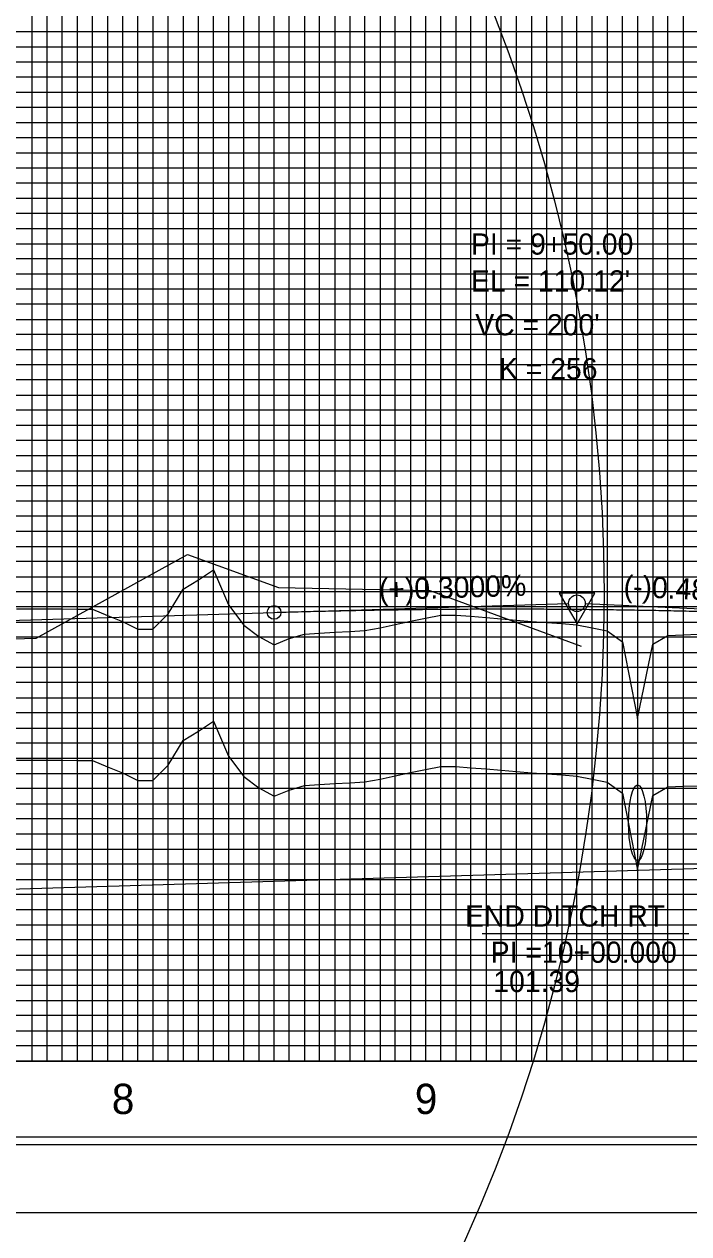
# Model space of a CAD drawing. Extents: x 2345490 to 2436403, y 465165 to 573888.
# Drawn here: x 2411662.8 to 2411882.2, y 527715 to 528114.5 of the extents above; entities that cross this region are included whole.
import ezdxf

# ---------------------------------------------------------------- set-up
doc = ezdxf.new("R2010")
doc.units = 0
for name, color, linetype in [('Old_Level_1', 7, 'Continuous'), ('Old_Level_18', 7, 'Continuous'), ('Old_Level_2', 7, 'Continuous'), ('Old_Level_3', 7, 'Continuous'), ('Old_Level_4', 7, 'Continuous'), ('Old_Level_41', 7, 'Continuous'), ('Old_Level_42', 7, 'Continuous'), ('Old_Level_43', 7, 'Continuous'), ('Old_Level_50', 7, 'Continuous'), ('Old_Level_51', 7, 'Continuous'), ('Old_Level_62', 7, 'Continuous'), ('Old_Level_63', 7, 'Continuous')]:
    doc.layers.add(name, color=color, linetype=linetype)

msp = doc.modelspace()

# ---------------------------------------------------------------- linework, layer by layer
at = {"layer": 'Old_Level_1'}
msp.add_lwpolyline([(2411660.325, 527871.39675), (2411665.325, 527871.40325), (2411670.325, 527871.4), (2411675.325, 527871.387), (2411680.325, 527871.364), (2411685.325, 527871.33125), (2411690.325, 527869.2045), (2411695.325, 527867.2145), (2411700.325, 527864.6685), (2411705.325, 527864.74925), (2411710.325, 527869.74075), (2411715.325, 527877.96775), (2411720.325, 527881.0285), (2411725.325, 527884.32975), (2411730.325, 527872.71875), (2411735.325, 527866.0195), (2411740.325, 527862.33025), (2411745.325, 527859.488), (2411750.325, 527861.572), (2411755.325, 527863.093), (2411760.325, 527863.4175), (2411765.325, 527863.7135), (2411770.325, 527863.98125), (2411775.325, 527864.2205), (2411780.325, 527865.149), (2411785.325, 527866.243), (2411790.325, 527867.30725), (2411795.325, 527868.34125), (2411800.325, 527869.3455), (2411805.325, 527869.375), (2411810.325, 527868.94925), (2411815.325, 527868.52725), (2411820.325, 527868.1085), (2411825.325, 527867.6935), (2411830.325, 527867.28175), (2411835.325, 527866.8735), (2411840.325, 527866.55275), (2411845.325, 527866.1855), (2411850.325, 527865.1565), (2411855.325, 527864.12875), (2411860.325, 527860.572), (2411865.325, 527835.20325), (2411870.325, 527859.79525), (2411875.325, 527862.6535), (2411880.325, 527862.82425), (2411885.325, 527862.99775)], dxfattribs=at)
at = {"layer": 'Old_Level_18'}
msp.add_lwpolyline([(2412345.325, 528797.04275), (2410845.325, 528797.04275), (2410845.325, 527747.04275), (2412345.325, 527747.04275)], close=True, dxfattribs=at)
at = {"layer": 'Old_Level_2'}
for p, q in [((2411745.325, 527920.243), (2411842.57625, 527923.16075)), ((2411945.325, 527918.443), (2411848.072, 527923.11125)), ((2411490.325, 527912.593), (2411745.325, 527920.243))]:
    msp.add_line(p, q, dxfattribs=at)
msp.add_lwpolyline([(2411851.19225, 527926.6255), (2411839.44975, 527926.611), (2411845.33325, 527916.49275)], close=True, dxfattribs=at)
for centre, radius in [((2411845.325, 527923.243), 2.75), ((2411745.325, 527920.243), 2.25)]:
    msp.add_circle(centre, radius, dxfattribs=at)
msp.add_spline([(2411745.325, 527920.243), (2411749.325, 527920.36), (2411753.325, 527920.47075), (2411757.325, 527920.575), (2411761.325, 527920.67325), (2411765.325, 527920.765), (2411769.325, 527920.85075), (2411773.325, 527920.93025), (2411777.325, 527921.0035), (2411781.325, 527921.0705), (2411785.325, 527921.131), (2411789.325, 527921.1855), (2411793.325, 527921.23375), (2411797.325, 527921.27575), (2411801.325, 527921.3115), (2411805.325, 527921.341), (2411809.325, 527921.3645), (2411813.325, 527921.3815), (2411817.325, 527921.39225), (2411821.325, 527921.39675), (2411825.325, 527921.395), (2411829.325, 527921.38725), (2411833.325, 527921.373), (2411837.325, 527921.35275), (2411841.325, 527921.326), (2411845.325, 527921.293), (2411849.325, 527921.254), (2411853.325, 527921.20875), (2411857.325, 527921.157), (2411861.325, 527921.09925), (2411865.325, 527921.035), (2411869.325, 527920.96475), (2411873.325, 527920.88825), (2411877.325, 527920.8055), (2411881.325, 527920.7165), (2411885.325, 527920.621), (2411889.325, 527920.5195), (2411893.325, 527920.41175), (2411897.325, 527920.29775), (2411901.325, 527920.1775), (2411905.325, 527920.051), (2411909.325, 527919.9185), (2411913.325, 527919.7795), (2411917.325, 527919.63425), (2411921.325, 527919.48275), (2411925.325, 527919.325), (2411929.325, 527919.16125), (2411933.325, 527918.991), (2411937.325, 527918.81475), (2411941.325, 527918.632), (2411945.325, 527918.443)], degree=3, dxfattribs=at)
at = {"layer": 'Old_Level_3'}
for p, q in [((2411407.325, 527821.24275), (2411895.325, 527835.94275)), ((2411814.00689, 527814.22607), (2411882.22664, 527814.22607))]:
    msp.add_line(p, q, dxfattribs=at)
at = {"layer": 'Old_Level_4'}
msp.add_ellipse((2411865.325, 527850.74275), major_axis=(0, 12.5), ratio=0.238746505, dxfattribs=at)
at = {"layer": 'Old_Level_41'}
msp.add_line((2412345.325, 527772.04275), (2410845.325, 527772.04275), dxfattribs=at)
for points in [[(2411670.325, 528797.04275), (2411670.325, 527772.04275), (2411720.325, 527772.04275), (2411720.325, 528797.04275)], [(2411695.325, 528797.04275), (2411695.325, 527772.04275), (2411745.325, 527772.04275), (2411745.325, 528797.04275)], [(2411770.325, 528797.04275), (2411770.325, 527772.04275), (2411820.325, 527772.04275), (2411820.325, 528797.04275)], [(2411795.325, 528797.04275), (2411795.325, 527772.04275), (2411845.325, 527772.04275), (2411845.325, 528797.04275)], [(2411870.325, 528797.04275), (2411870.325, 527772.04275), (2411920.325, 527772.04275), (2411920.325, 528797.04275)], [(2412345.325, 528097.04275), (2410845.325, 528097.04275), (2410845.325, 528047.04275), (2412345.325, 528047.04275)], [(2412345.325, 528022.04275), (2410845.325, 528022.04275), (2410845.325, 528072.04275), (2412345.325, 528072.04275)], [(2412345.325, 527997.04275), (2410845.325, 527997.04275), (2410845.325, 527947.04275), (2412345.325, 527947.04275)], [(2412345.325, 527897.04275), (2410845.325, 527897.04275), (2410845.325, 527847.04275), (2412345.325, 527847.04275)], [(2412345.325, 527822.04275), (2410845.325, 527822.04275), (2410845.325, 527872.04275), (2412345.325, 527872.04275)], [(2412345.325, 527797.04275), (2410845.325, 527797.04275)]]:
    msp.add_lwpolyline(points, dxfattribs=at)
at = {"layer": 'Old_Level_42'}
msp.add_lwpolyline([(2412345.325, 527922.04275), (2410845.325, 527922.04275), (2410845.325, 527972.04275), (2412345.325, 527972.04275)], dxfattribs=at)
at = {"layer": 'Old_Level_43'}
for points in [[(2411665.325, 528797.04275), (2411665.325, 527772.04275), (2411675.325, 527772.04275), (2411675.325, 528797.04275)], [(2411680.325, 528797.04275), (2411680.325, 527772.04275), (2411685.325, 527772.04275), (2411685.325, 528797.04275)], [(2411690.325, 528797.04275), (2411690.325, 527772.04275), (2411700.325, 527772.04275), (2411700.325, 528797.04275)], [(2411705.325, 528797.04275), (2411705.325, 527772.04275), (2411710.325, 527772.04275), (2411710.325, 528797.04275)], [(2411715.325, 528797.04275), (2411715.325, 527772.04275), (2411725.325, 527772.04275), (2411725.325, 528797.04275)], [(2411730.325, 528797.04275), (2411730.325, 527772.04275), (2411735.325, 527772.04275), (2411735.325, 528797.04275)], [(2411740.325, 528797.04275), (2411740.325, 527772.04275), (2411750.325, 527772.04275), (2411750.325, 528797.04275)], [(2411755.325, 528797.04275), (2411755.325, 527772.04275), (2411760.325, 527772.04275), (2411760.325, 528797.04275)], [(2411765.325, 528797.04275), (2411765.325, 527772.04275), (2411775.325, 527772.04275), (2411775.325, 528797.04275)], [(2411780.325, 528797.04275), (2411780.325, 527772.04275), (2411785.325, 527772.04275), (2411785.325, 528797.04275)], [(2411790.325, 528797.04275), (2411790.325, 527772.04275), (2411800.325, 527772.04275), (2411800.325, 528797.04275)], [(2411805.325, 528797.04275), (2411805.325, 527772.04275), (2411810.325, 527772.04275), (2411810.325, 528797.04275)], [(2411815.325, 528797.04275), (2411815.325, 527772.04275), (2411825.325, 527772.04275), (2411825.325, 528797.04275)], [(2411830.325, 528797.04275), (2411830.325, 527772.04275), (2411835.325, 527772.04275), (2411835.325, 528797.04275)], [(2411840.325, 528797.04275), (2411840.325, 527772.04275), (2411850.325, 527772.04275), (2411850.325, 528797.04275)], [(2411855.325, 528797.04275), (2411855.325, 527772.04275), (2411860.325, 527772.04275), (2411860.325, 528797.04275)], [(2411865.325, 528797.04275), (2411865.325, 527772.04275), (2411875.325, 527772.04275), (2411875.325, 528797.04275)], [(2411880.325, 528797.04275), (2411880.325, 527772.04275), (2411885.325, 527772.04275), (2411885.325, 528797.04275)], [(2412295.325, 528112.04275), (2410895.325, 528112.04275), (2410895.325, 528107.04275), (2412295.325, 528107.04275)], [(2412295.325, 528102.04275), (2410895.325, 528102.04275), (2410895.325, 528092.04275), (2412295.325, 528092.04275)], [(2412295.325, 528087.04275), (2410895.325, 528087.04275), (2410895.325, 528082.04275), (2412295.325, 528082.04275)], [(2412295.325, 528077.04275), (2410895.325, 528077.04275), (2410895.325, 528067.04275), (2412295.325, 528067.04275)], [(2412295.325, 528062.04275), (2410895.325, 528062.04275), (2410895.325, 528057.04275), (2412295.325, 528057.04275)], [(2412295.325, 528052.04275), (2410895.325, 528052.04275), (2410895.325, 528042.04275), (2412295.325, 528042.04275)], [(2412295.325, 528037.04275), (2410895.325, 528037.04275), (2410895.325, 528032.04275), (2412295.325, 528032.04275)], [(2412295.325, 528027.04275), (2410895.325, 528027.04275), (2410895.325, 528017.04275), (2412295.325, 528017.04275)], [(2412295.325, 528012.04275), (2410895.325, 528012.04275), (2410895.325, 528007.04275), (2412295.325, 528007.04275)], [(2412295.325, 528002.04275), (2410895.325, 528002.04275), (2410895.325, 527992.04275), (2412295.325, 527992.04275)], [(2412295.325, 527987.04275), (2410895.325, 527987.04275), (2410895.325, 527982.04275), (2412295.325, 527982.04275)], [(2412295.325, 527977.04275), (2410895.325, 527977.04275)], [(2410895.325, 527967.04275), (2412295.325, 527967.04275)], [(2412295.325, 527962.04275), (2410895.325, 527962.04275), (2410895.325, 527957.04275), (2412295.325, 527957.04275)], [(2412295.325, 527952.04275), (2410895.325, 527952.04275)], [(2410895.325, 527942.04275), (2412295.325, 527942.04275)], [(2412295.325, 527937.04275), (2410895.325, 527937.04275), (2410895.325, 527932.04275), (2412295.325, 527932.04275)], [(2412295.325, 527927.04275), (2410895.325, 527927.04275), (2410895.325, 527917.04275), (2412295.325, 527917.04275)], [(2412295.325, 527912.04275), (2410895.325, 527912.04275), (2410895.325, 527907.04275), (2412295.325, 527907.04275)], [(2412295.325, 527902.04275), (2410895.325, 527902.04275), (2410895.325, 527892.04275), (2412295.325, 527892.04275)], [(2412295.325, 527887.04275), (2410895.325, 527887.04275), (2410895.325, 527882.04275), (2412295.325, 527882.04275)], [(2412295.325, 527877.04275), (2410895.325, 527877.04275), (2410895.325, 527867.04275), (2412295.325, 527867.04275)], [(2412295.325, 527862.04275), (2410895.325, 527862.04275), (2410895.325, 527857.04275), (2412295.325, 527857.04275)], [(2412295.325, 527852.04275), (2410895.325, 527852.04275), (2410895.325, 527842.04275), (2412295.325, 527842.04275)], [(2412295.325, 527837.04275), (2410895.325, 527837.04275), (2410895.325, 527832.04275), (2412295.325, 527832.04275)], [(2412295.325, 527827.04275), (2410895.325, 527827.04275), (2410895.325, 527817.04275), (2412295.325, 527817.04275)], [(2412295.325, 527812.04275), (2410895.325, 527812.04275), (2410895.325, 527807.04275), (2412295.325, 527807.04275)], [(2412295.325, 527802.04275), (2410895.325, 527802.04275), (2410895.325, 527792.04275), (2412295.325, 527792.04275)], [(2412295.325, 527787.04275), (2410895.325, 527787.04275), (2410895.325, 527782.04275), (2412295.325, 527782.04275)], [(2412295.325, 527777.04275), (2410895.325, 527777.04275)]]:
    msp.add_lwpolyline(points, dxfattribs=at)
at = {"layer": 'Old_Level_50'}
msp.add_lwpolyline([(2412357.825, 528799.59275), (2410691.325, 528799.59275), (2410691.325, 527744.49275), (2412357.825, 527744.49275)], close=True, dxfattribs=at)
at = {"layer": 'Old_Level_51'}
msp.add_lwpolyline([(2412362.325, 528822.04275), (2410678.325, 528822.04275), (2410678.325, 527722.04275), (2412362.325, 527722.04275)], close=True, dxfattribs=at)
at = {"layer": 'Old_Level_62'}
msp.add_circle((2411335.51705, 527926.51577), 518.74216, dxfattribs=at)
at = {"layer": 'Old_Level_63'}
msp.add_line((2410895.325, 527772.04275), (2413081.64925, 527772.04275), dxfattribs=at)
for points in [[(2410937.46001, 527957.6808), (2410986.64001, 527948.9808), (2411035.83001, 527950.0808), (2411085.01001, 527951.5808), (2411134.21001, 527939.5808), (2411183.43001, 527923.9808), (2411232.67001, 527920.7808), (2411281.95001, 527917.6808), (2411331.27001, 527914.4808), (2411380.65001, 527911.1808), (2411426.73001, 527909.8808), (2411471.73001, 527905.9808), (2411521.73001, 527907.3808), (2411571.73001, 527908.8808), (2411616.73001, 527910.2808), (2411666.73001, 527911.7808), (2411716.73001, 527939.3808), (2411746.73001, 527928.4808), (2411796.73001, 527927.4808), (2411846.73001, 527909.0808)], [(2411660.325, 527921.39675), (2411665.325, 527921.40325), (2411670.325, 527921.4), (2411675.325, 527921.387), (2411680.325, 527921.364), (2411685.325, 527921.33125), (2411690.325, 527919.2045), (2411695.325, 527917.2145), (2411700.325, 527914.6685), (2411705.325, 527914.74925), (2411710.325, 527919.74075), (2411715.325, 527927.96775), (2411720.325, 527931.0285), (2411725.325, 527934.32975), (2411730.325, 527922.71875), (2411735.325, 527916.0195), (2411740.325, 527912.33025), (2411745.325, 527909.488), (2411750.325, 527911.572), (2411755.325, 527913.093), (2411760.325, 527913.4175), (2411765.325, 527913.7135), (2411770.325, 527913.98125), (2411775.325, 527914.2205), (2411780.325, 527915.149), (2411785.325, 527916.243), (2411790.325, 527917.30725), (2411795.325, 527918.34125), (2411800.325, 527919.3455), (2411805.325, 527919.375), (2411810.325, 527918.94925), (2411815.325, 527918.52725), (2411820.325, 527918.1085), (2411825.325, 527917.6935), (2411830.325, 527917.28175), (2411835.325, 527916.8735), (2411840.325, 527916.55275), (2411845.325, 527916.1855), (2411850.325, 527915.1565), (2411855.325, 527914.12875), (2411860.325, 527910.572), (2411865.325, 527885.20325), (2411870.325, 527909.79525), (2411875.325, 527912.6535), (2411880.325, 527912.82425), (2411885.325, 527912.99775)]]:
    msp.add_lwpolyline(points, dxfattribs=at)

# ---------------------------------------------------------------- texts
at = {"layer": 'Old_Level_2'}
for s, height, p in [('PI = 9+50.00', 7.0000005, (2411810.32525, 528038.42125)), ("EL = 110.12'", 7.0000005, (2411810.325, 528026.243)), ("VC = 200'", 7.000001, (2411811.74925, 528011.76325)), ('K = 256', 7.000001, (2411819.56825, 527997.23675))]:
    msp.add_text(s, height=height, dxfattribs=at).set_placement(p)
for s, rotation, p in [('(+)0.3000%', 1.7183583, (2411780.025, 527924.28575)), ('(-)0.4800%', 357.2519111, (2411860.5975, 527925.5135))]:
    msp.add_text(s, height=7.000001, rotation=rotation, dxfattribs=at).set_placement(p)
at = {"layer": 'Old_Level_3'}
for s, height, p in [('END DITCH RT', 7.0000005, (2411808.35929, 527816.46896)), ('PI =10+00.000', 7.0000005, (2411816.85027, 527804.48586)), ('101.39', 7.000001, (2411817.68882, 527794.81533))]:
    msp.add_text(s, height=height, rotation=360, dxfattribs=at).set_placement(p)
at = {"layer": 'Old_Level_62'}
for s, p in [('8', (2411691.748, 527754.543)), ('9', (2411791.79025, 527754.543))]:
    msp.add_text(s, height=10, dxfattribs=at).set_placement(p)

doc.saveas('drawing.dxf')
